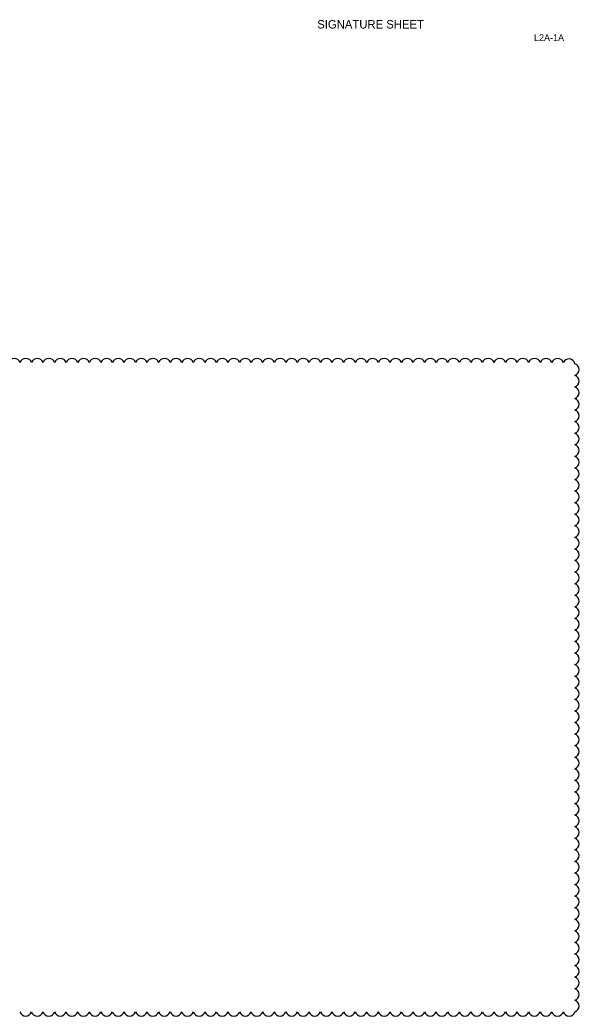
# Model space of a CAD drawing. Extents: x -811 to 10319, y -2309 to 9962.
# Drawn here: x -803.6 to -795.32, y -2213.66 to -2198.93 of the extents above; entities that cross this region are included whole.
import ezdxf

# ---------------------------------------------------------------- set-up
doc = ezdxf.new("R2010")
doc.units = 0
for name, color, linetype in [('PlotBorder_dp', 7, 'Continuous'), ('SheetLines_dp', 7, 'Continuous'), ('TextTitle', 7, 'Continuous')]:
    doc.layers.add(name, color=color, linetype=linetype)

msp = doc.modelspace()

# ---------------------------------------------------------------- linework, layer by layer
at = {"layer": 'TextTitle'}
for centre, radius, start, end in [((-803.684, -2204.028), 0.0897, 17.5, 162.5), ((-803.513, -2204.028), 0.0897, 17.5, 162.5), ((-803.342, -2204.028), 0.0897, 17.5, 162.5), ((-803.171, -2204.028), 0.0897, 17.5, 162.5), ((-803, -2204.028), 0.0897, 17.5, 162.5), ((-802.829, -2204.028), 0.0897, 17.5, 162.5), ((-802.657, -2204.028), 0.0897, 17.5, 162.5), ((-802.486, -2204.028), 0.0897, 17.5, 162.5), ((-802.315, -2204.028), 0.0897, 17.5, 162.5), ((-802.144, -2204.028), 0.0897, 17.5, 162.5), ((-801.973, -2204.028), 0.0897, 17.5, 162.5), ((-801.802, -2204.028), 0.0897, 17.5, 162.5), ((-801.631, -2204.028), 0.0897, 17.5, 162.5), ((-801.46, -2204.028), 0.0897, 17.5, 162.5), ((-801.288, -2204.028), 0.0897, 17.5, 162.5), ((-801.117, -2204.028), 0.0897, 17.5, 162.5), ((-800.946, -2204.028), 0.0897, 17.5, 162.5), ((-800.775, -2204.028), 0.0897, 17.5, 162.5), ((-800.604, -2204.028), 0.0897, 17.5, 162.5), ((-800.433, -2204.028), 0.0897, 17.5, 162.5), ((-800.262, -2204.028), 0.0897, 17.5, 162.5), ((-800.091, -2204.028), 0.0897, 17.5, 162.5), ((-799.919, -2204.028), 0.0897, 17.5, 162.5), ((-799.748, -2204.028), 0.0897, 17.5, 162.5), ((-799.577, -2204.028), 0.0897, 17.5, 162.5), ((-799.406, -2204.028), 0.0897, 17.5, 162.5), ((-799.235, -2204.028), 0.0897, 17.5, 162.5), ((-799.064, -2204.028), 0.0897, 17.5, 162.5), ((-798.893, -2204.028), 0.0897, 17.5, 162.5), ((-798.722, -2204.028), 0.0897, 17.5, 162.5), ((-798.551, -2204.028), 0.0897, 17.5, 162.5), ((-798.379, -2204.028), 0.0897, 17.5, 162.5), ((-798.208, -2204.028), 0.0897, 17.5, 162.5), ((-798.037, -2204.028), 0.0897, 17.5, 162.5), ((-797.866, -2204.028), 0.0897, 17.5, 162.5), ((-797.695, -2204.028), 0.0897, 17.5, 162.5), ((-797.524, -2204.028), 0.0897, 17.5, 162.5), ((-797.353, -2204.028), 0.0897, 17.5, 162.5), ((-797.182, -2204.028), 0.0897, 17.5, 162.5), ((-797.01, -2204.028), 0.0897, 17.5, 162.5), ((-796.839, -2204.028), 0.0897, 17.5, 162.5), ((-796.668, -2204.028), 0.0897, 17.5, 162.5), ((-796.497, -2204.028), 0.0897, 17.5, 162.5), ((-796.326, -2204.028), 0.0897, 17.5, 162.5), ((-796.155, -2204.028), 0.0897, 17.5, 162.5), ((-795.984, -2204.028), 0.0897, 17.5, 162.5), ((-795.813, -2204.028), 0.0897, 17.5, 162.5), ((-795.641, -2204.028), 0.0897, 17.5, 162.5), ((-795.474, -2204.036), 0.0896, 11.7454, 156.7454), ((-795.413, -2204.103), 0.0897, 287.5, 72.5), ((-795.413, -2204.274), 0.0897, 287.5, 72.5), ((-795.413, -2204.446), 0.0897, 287.5, 72.5), ((-795.413, -2204.617), 0.0897, 287.5, 72.5), ((-795.413, -2204.788), 0.0897, 287.5, 72.5), ((-795.413, -2204.959), 0.0897, 287.5, 72.5), ((-795.413, -2205.13), 0.0897, 287.5, 72.5), ((-795.413, -2205.301), 0.0897, 287.5, 72.5), ((-795.413, -2205.472), 0.0897, 287.5, 72.5), ((-795.413, -2205.643), 0.0897, 287.5, 72.5), ((-795.413, -2205.815), 0.0897, 287.5, 72.5), ((-795.413, -2205.986), 0.0897, 287.5, 72.5), ((-795.413, -2206.157), 0.0897, 287.5, 72.5), ((-795.413, -2206.328), 0.0897, 287.5, 72.5), ((-795.413, -2206.499), 0.0897, 287.5, 72.5), ((-795.413, -2206.67), 0.0897, 287.5, 72.5), ((-795.413, -2206.841), 0.0897, 287.5, 72.5), ((-795.413, -2207.012), 0.0897, 287.5, 72.5), ((-795.413, -2207.184), 0.0897, 287.5, 72.5), ((-795.413, -2207.355), 0.0897, 287.5, 72.5), ((-795.413, -2207.526), 0.0897, 287.5, 72.5), ((-795.413, -2207.697), 0.0897, 287.5, 72.5), ((-795.413, -2207.868), 0.0897, 287.5, 72.5), ((-795.413, -2208.039), 0.0897, 287.5, 72.5), ((-795.413, -2208.21), 0.0897, 287.5, 72.5), ((-795.413, -2208.381), 0.0897, 287.5, 72.5), ((-795.413, -2208.553), 0.0897, 287.5, 72.5), ((-795.413, -2208.724), 0.0897, 287.5, 72.5), ((-795.413, -2208.895), 0.0897, 287.5, 72.5), ((-795.413, -2209.066), 0.0897, 287.5, 72.5), ((-795.413, -2209.237), 0.0897, 287.5, 72.5), ((-795.413, -2209.408), 0.0897, 287.5, 72.5), ((-795.413, -2209.579), 0.0897, 287.5, 72.5), ((-795.413, -2209.75), 0.0897, 287.5, 72.5), ((-795.413, -2209.922), 0.0897, 287.5, 72.5), ((-795.413, -2210.093), 0.0897, 287.5, 72.5), ((-795.413, -2210.264), 0.0897, 287.5, 72.5), ((-795.413, -2210.435), 0.0897, 287.5, 72.5), ((-795.413, -2210.606), 0.0897, 287.5, 72.5), ((-795.413, -2210.777), 0.0897, 287.5, 72.5), ((-795.413, -2210.948), 0.0897, 287.5, 72.5), ((-795.413, -2211.119), 0.0897, 287.5, 72.5), ((-795.413, -2211.29), 0.0897, 287.5, 72.5), ((-795.413, -2211.462), 0.0897, 287.5, 72.5), ((-795.413, -2211.633), 0.0897, 287.5, 72.5), ((-795.413, -2211.804), 0.0897, 287.5, 72.5), ((-795.413, -2211.975), 0.0897, 287.5, 72.5), ((-795.413, -2212.146), 0.0897, 287.5, 72.5), ((-795.413, -2212.317), 0.0897, 287.5, 72.5), ((-795.413, -2212.488), 0.0897, 287.5, 72.5), ((-795.413, -2212.659), 0.0897, 287.5, 72.5), ((-795.413, -2212.831), 0.0897, 287.5, 72.5), ((-795.413, -2213.002), 0.0897, 287.5, 72.5), ((-795.413, -2213.173), 0.0897, 287.5, 72.5), ((-795.413, -2213.344), 0.0897, 287.5, 72.5), ((-795.413, -2213.515), 0.0897, 287.5, 72.5), ((-803.514, -2213.574), 0.0897, 197.5, 342.5), ((-803.343, -2213.574), 0.0897, 197.5, 342.5), ((-803.172, -2213.574), 0.0897, 197.5, 342.5), ((-803.001, -2213.574), 0.0897, 197.5, 342.5), ((-802.83, -2213.574), 0.0897, 197.5, 342.5), ((-802.658, -2213.574), 0.0897, 197.5, 342.5), ((-802.487, -2213.574), 0.0897, 197.5, 342.5), ((-802.316, -2213.574), 0.0897, 197.5, 342.5), ((-802.145, -2213.574), 0.0897, 197.5, 342.5), ((-801.974, -2213.574), 0.0897, 197.5, 342.5), ((-801.803, -2213.574), 0.0897, 197.5, 342.5), ((-801.632, -2213.574), 0.0897, 197.5, 342.5), ((-801.461, -2213.574), 0.0897, 197.5, 342.5), ((-801.289, -2213.574), 0.0897, 197.5, 342.5), ((-801.118, -2213.574), 0.0897, 197.5, 342.5), ((-800.947, -2213.574), 0.0897, 197.5, 342.5), ((-800.776, -2213.574), 0.0897, 197.5, 342.5), ((-800.605, -2213.574), 0.0897, 197.5, 342.5), ((-800.434, -2213.574), 0.0897, 197.5, 342.5), ((-800.263, -2213.574), 0.0897, 197.5, 342.5), ((-800.092, -2213.574), 0.0897, 197.5, 342.5), ((-799.921, -2213.574), 0.0897, 197.5, 342.5), ((-799.749, -2213.574), 0.0897, 197.5, 342.5), ((-799.578, -2213.574), 0.0897, 197.5, 342.5), ((-799.407, -2213.574), 0.0897, 197.5, 342.5), ((-799.236, -2213.574), 0.0897, 197.5, 342.5), ((-799.065, -2213.574), 0.0897, 197.5, 342.5), ((-798.894, -2213.574), 0.0897, 197.5, 342.5), ((-798.723, -2213.574), 0.0897, 197.5, 342.5), ((-798.552, -2213.574), 0.0897, 197.5, 342.5), ((-798.38, -2213.574), 0.0897, 197.5, 342.5), ((-798.209, -2213.574), 0.0897, 197.5, 342.5), ((-798.038, -2213.574), 0.0897, 197.5, 342.5), ((-797.867, -2213.574), 0.0897, 197.5, 342.5), ((-797.696, -2213.574), 0.0897, 197.5, 342.5), ((-797.525, -2213.574), 0.0897, 197.5, 342.5), ((-797.354, -2213.574), 0.0897, 197.5, 342.5), ((-797.183, -2213.574), 0.0897, 197.5, 342.5), ((-797.011, -2213.574), 0.0897, 197.5, 342.5), ((-796.84, -2213.574), 0.0897, 197.5, 342.5), ((-796.669, -2213.574), 0.0897, 197.5, 342.5), ((-796.498, -2213.574), 0.0897, 197.5, 342.5), ((-796.327, -2213.574), 0.0897, 197.5, 342.5), ((-796.156, -2213.574), 0.0897, 197.5, 342.5), ((-795.985, -2213.574), 0.0897, 197.5, 342.5), ((-795.814, -2213.574), 0.0897, 197.5, 342.5), ((-795.642, -2213.574), 0.0897, 197.5, 342.5), ((-795.471, -2213.574), 0.0897, 197.5, 342.5)]:
    msp.add_arc(centre, radius, start, end, dxfattribs=at)

# ---------------------------------------------------------------- texts
at = {"layer": 'PlotBorder_dp'}
msp.add_text('       SIGNATURE SHEET         ', height=0.125, dxfattribs=at).set_placement((-799.524, -2199.06))
at = {"layer": 'SheetLines_dp'}
msp.add_text('L2A-1A', height=0.1, dxfattribs=at).set_placement((-795.991, -2199.246))

doc.saveas('drawing.dxf')
